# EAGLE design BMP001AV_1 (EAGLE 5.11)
AUTHOR: Nigel Batten; DATE: 15th Jun 2012; PRODUCT: AV XMega PDI - BMP001AV; RANGE: BreadMate; VERSION: Sch v1
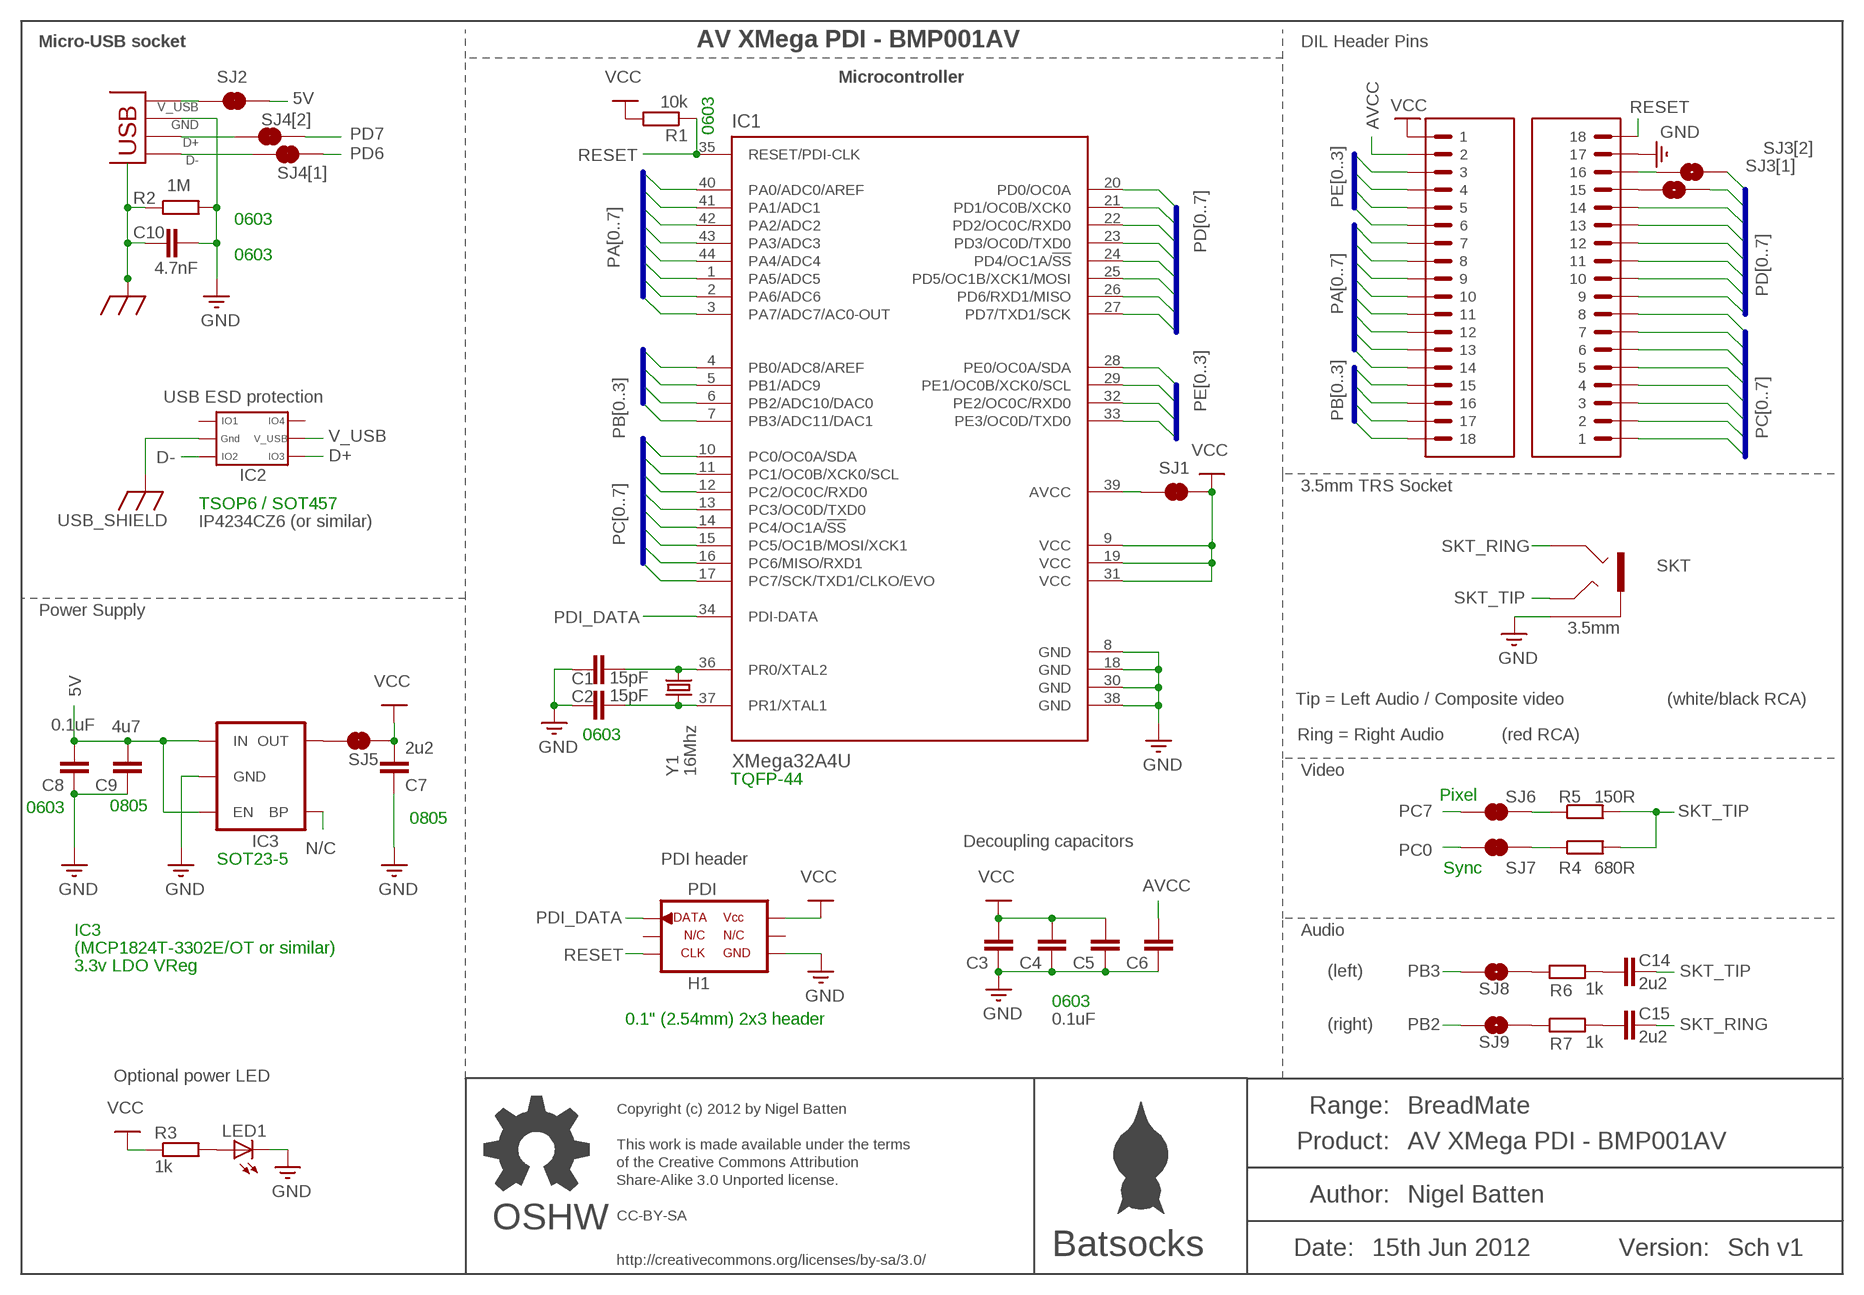
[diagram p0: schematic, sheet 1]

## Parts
C1  15pF  C_EU0603_TIGHT_MARK  [C0603TM]
C2  15pF  C_EU0603_TIGHT_MARK  [C0603TM]
C3  0.1uF  C_EU0603_TIGHT_MARK  [C0603TM]
C4  0.1uF  C_EU0603_TIGHT_MARK  [C0603TM]
C5  0.1uF  C_EU0603_TIGHT_MARK  [C0603TM]
C6  0.1uF  C_EU0603_TIGHT_MARK  [C0603TM]
C7  2u2  C_EU0805TM  [C0805TM]
C8  0.1uF  C_EU0603_TIGHT_MARK  [C0603TM]
C9  4u7  C_EU0805TM  [C0805TM]
C10  4.7nF  C_EU0603_TIGHT_MARK  [C0603TM]
C14  2u2  C_EU0603_TIGHT_MARK  [C0603TM]
C15  2u2  C_EU0603_TIGHT_MARK  [C0603TM]
H1  PDI  AVR_PDI_6  [AVR_ISP_6]
IC1  XMega32A4U  AT-XMEGA-XXA4-AUMEDIUM  [TQFP44_M]
IC2  USB_ESD  [SOT457]
IC3  LDO  V_REG_LDOSMD  [SOT23-5]
LED1  LED0603TU  [D0603TU]
R1  10k  RESISTOR0603_TIGHT_MARKED  [R0603TM]
R2  1M  RESISTOR0603_TIGHT_MARKED  [R0603TM]
R3  1k  RESISTOR0603TU  [R0603TU]
R4  680R  RESISTOR0603_TIGHT_MARKED  [R0603TM]
R5  150R  RESISTOR0603_TIGHT_MARKED  [R0603TM]
R6  1k  RESISTOR0603_TIGHT_MARKED  [R0603TM]
R7  1k  RESISTOR0603_TIGHT_MARKED  [R0603TM]
SJ1  SOLDERJUMPER_NCUNMARKED  [SJ_NC_U]
SJ2  SOLDERJUMPER_NCUNMARKED  [SJ_NC_U]
SJ3[1]  SOLDERJUMPER_NOSMALL_UNMARKED  [SJ_NO_SMALL_U]
SJ3[2]  SOLDERJUMPER_NOSMALL_UNMARKED  [SJ_NO_SMALL_U]
SJ4[1]  SOLDERJUMPER_NCSMALL_UNMARKED  [SJ_NC_SMALL_U]
SJ4[2]  SOLDERJUMPER_NCSMALL_UNMARKED  [SJ_NC_SMALL_U]
SJ5  SOLDERJUMPER_NCUNMARKED  [SJ_NC_U]
SJ6  SOLDERJUMPER_NCSMALL_UNMARKED  [SJ_NC_SMALL_U]
SJ7  SOLDERJUMPER_NCSMALL_UNMARKED  [SJ_NC_SMALL_U]
SJ8  SOLDERJUMPER_NOSMALL_UNMARKED  [SJ_NO_SMALL_U]
SJ9  SOLDERJUMPER_NOSMALL_UNMARKED  [SJ_NO_SMALL_U]
SKT  3.5mm  STEREO_SOCKET_UNSWITCHEDSMT  [SKT_STEREO_3.5MM_SMT_PJ313D]
U$2  HEADER_18BIGPADS_UNMARKED  [HEADER_18_BIGPADS_UNMARKED]
U$3  HEADER_18BIGPADS_UNMARKED  [HEADER_18_BIGPADS_UNMARKED]
U$4  LOGO_BATSOCKSTINY  [LOGO_BATSOCKS_TINY]
U$5  LOGO_OSHWTINY  [LOGO_OSHW_TINY]
USB  USB_SHIELD_8  [USB_MICRO_B]
Y1  16Mhz  CRYSTAL_4PINFA238_U  [CRYSTAL_FA238_U]

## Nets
5V: C8.2 C9.2 IC3.1(IN) IC3.3(EN) SJ2.2
AVCC: C6.2 IC1.39(AVCC) SJ1.2 U$2.P$2
D+: IC2.P$4(IO3) SJ4[2].1 USB.D+
D-: IC2.P$3(IO2) SJ4[1].1 USB.D-
GND: C1.2 C2.2 C3.1 C4.1 C5.1 C6.1 C7.2 C8.1 C9.1 C10.1 H1.P$6(GND) IC1.8(GND) IC1.18(GND) IC1.30(GND) IC1.38(GND) IC3.2(GND) LED1.K(C) R2.2 SKT.P$2(S) U$3.P$17 USB.GND
N$1: C2.1 IC1.37(PR1/XTAL1) Y1.P$1
N$2: C1.1 IC1.36(PR0/XTAL2) Y1.P$3
N$3: SJ3[1].1 U$3.P$15
N$4: SJ3[2].1 U$3.P$16
N$5: LED1.A R3.2
N$6: IC3.5(OUT) SJ5.1
N$7: R6.1 SJ8.2
N$8: R4.1 SJ7.2
N$9: R5.1 SJ6.2
N$11: R7.1 SJ9.2
N$12: C14.2 R6.2
N$13: C15.2 R7.2
N/C: IC3.4(BP)
PA0: IC1.40(PA0/ADC0/AREF) U$2.P$7
PA1: IC1.41(PA1/ADC1) U$2.P$8
PA2: IC1.42(PA2/ADC2) U$2.P$9
PA3: IC1.43(PA3/ADC3) U$2.P$10
PA4: IC1.44(PA4/ADC4) U$2.P$11
PA5: IC1.1(PA5/ADC5) U$2.P$12
PA6: IC1.2(PA6/ADC6) U$2.P$13
PA7: IC1.3(PA7/ADC7/AC0-OUT) U$2.P$14
PB0: IC1.4(PB0/ADC8/AREF) U$2.P$15
PB1: IC1.5(PB1/ADC9) U$2.P$16
PB2: IC1.6(PB2/ADC10/DAC0) SJ9.1 U$2.P$17
PB3: IC1.7(PB3/ADC11/DAC1) SJ8.1 U$2.P$18
PC0: IC1.10(PC0/OC0A/SDA) SJ7.1 U$3.P$1
PC1: IC1.11(PC1/OC0B/XCK0/SCL) U$3.P$2
PC2: IC1.12(PC2/OC0C/RXD0) U$3.P$3
PC3: IC1.13(PC3/OC0D/TXD0) U$3.P$4
PC4: IC1.14(PC4/OC1A/!SS) U$3.P$5
PC5: IC1.15(PC5/OC1B/MOSI/XCK1) U$3.P$6
PC6: IC1.16(PC6/MISO/RXD1) U$3.P$7
PC7: IC1.17(PC7/SCK/TXD1/CLKO/EVO) SJ6.1 U$3.P$8
PD0: IC1.20(PD0/OC0A) U$3.P$9
PD1: IC1.21(PD1/OC0B/XCK0) U$3.P$10
PD2: IC1.22(PD2/OC0C/RXD0) U$3.P$11
PD3: IC1.23(PD3/OC0D/TXD0) U$3.P$12
PD4: IC1.24(PD4/OC1A/!SS) U$3.P$13
PD5: IC1.25(PD5/OC1B/XCK1/MOSI) U$3.P$14
PD6: IC1.26(PD6/RXD1/MISO) SJ3[1].2 SJ4[1].2
PD7: IC1.27(PD7/TXD1/SCK) SJ3[2].2 SJ4[2].2
PDI_DATA: H1.P$1(DATA) IC1.34(PDI-DATA)
PE0: IC1.28(PE0/OC0A/SDA) U$2.P$3
PE1: IC1.29(PE1/OC0B/XCK0/SCL) U$2.P$4
PE2: IC1.32(PE2/OC0C/RXD0) U$2.P$5
PE3: IC1.33(PE3/OC0D/TXD0) U$2.P$6
RESET: H1.P$5(CLK) IC1.35(RESET/PDI-CLK) R1.1 U$3.P$18
SKT_RING: C15.1 SKT.P$3(R)
SKT_TIP: C14.1 R4.2 R5.2 SKT.P$4(T)
USB_SHIELD: C10.2 IC2.P$2(GND) R2.1 USB.SHIELD$1 USB.SHIELD$2(SHIELD$1) USB.SHIELD$3(SHIELD$1) USB.SHIELD$4(SHIELD$1) USB.SHIELD$5(SHIELD$1) USB.SHIELD$6(SHIELD$1) USB.SHIELD$7(SHIELD$1) USB.SHIELD$8(SHIELD$1) ; supply symbol labelled SHIELD
V_USB: IC2.P$5(V_USB) SJ2.1 USB.VBUS(V_USB)
VCC: C3.2 C4.2 C5.2 C7.1 H1.P$2(VCC_IO) IC1.9(VCC) IC1.19(VCC) IC1.31(VCC) R1.2 R3.1 SJ1.1 SJ5.2 U$2.P$1
Unconnected: H1.P$3(NC1) H1.P$4(NC2) IC2.P$1(IO1) IC2.P$6(IO4)

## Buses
PA[0..7]
PC[0..7]
PB[0..3]
PE[0..3]
PD[0..7]

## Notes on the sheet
- Micro-USB socket | DIL Header Pins
- Microcontroller
- 0603
- 0603
- 0603
- USB ESD protection
- 3.5mm TRS Socket
- TSOP6 / SOT457
- IP4234CZ6 (or similar)
- Power Supply
- Tip = Left Audio / Composite video | (white/black RCA)
- 0603 | Ring = Right Audio | (red RCA)
- Y1 | Video
- TQFP-44
- Pixel
- 0603 | 0805 | 0805
- Decoupling capacitors
- SOT23-5 | PDI header
- Sync
- IC3 | Audio
- (MCP1824T-3302E/OT or similar)
- 3.3v LDO VReg
- (left)
- 0603
- 0.1" (2.54mm) 2x3 header
- (right)
- Optional power LED
- Copyright (c) 2012 by Nigel Batten
- This work is made available under the terms
- of the Creative Commons Attribution
- Share-Alike 3.0 Unported license.
- CC-BY-SA
- OSHW
- http://creativecommons.org/licenses/by-sa/3.0/

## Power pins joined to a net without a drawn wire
GND$1: Y1.P$2(GND$1)
GND$2: Y1.P$4(GND$2)

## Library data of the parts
C1-C10 C14 C15 = Batten:C_EU
H1 = Batten:AVR_PDI_6
IC1 = Batten:AT-XMEGA-XXA4-AU: ATxMega a4 Series
IC2 = Batten:USB_ESD
IC3 = Batten:V_REG_LDO: Voltage Regulator LDO Standard 150mA LDO voltage regulator in SOT-23 layout. Micrel part MIC5205. BP (by-pass) pin is used to lower output noise with 470pF cap.
LED1 = Batten:LED: LED
R1-R7 = Batten:RESISTOR
SJ1 SJ2 SJ4[1] SJ4[2] SJ5-SJ7 = Batten:SOLDERJUMPER_NC: Solder Jumper
SJ3[1] SJ3[2] SJ8 SJ9 = Batten:SOLDERJUMPER_NO: Solder Jumper
SKT = Batten:STEREO_SOCKET_UNSWITCHED
U$2 U$3 = Batten:HEADER_18
U$4 = Batten:LOGO_BATSOCKS
U$5 = Batten:LOGO_OSHW
USB = Batten:USB_SHIELD_8
Y1 = Batten:CRYSTAL_4PIN

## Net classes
1 power: width 0.406 mm, drill 0.35 mm, clearance 0.203 mm

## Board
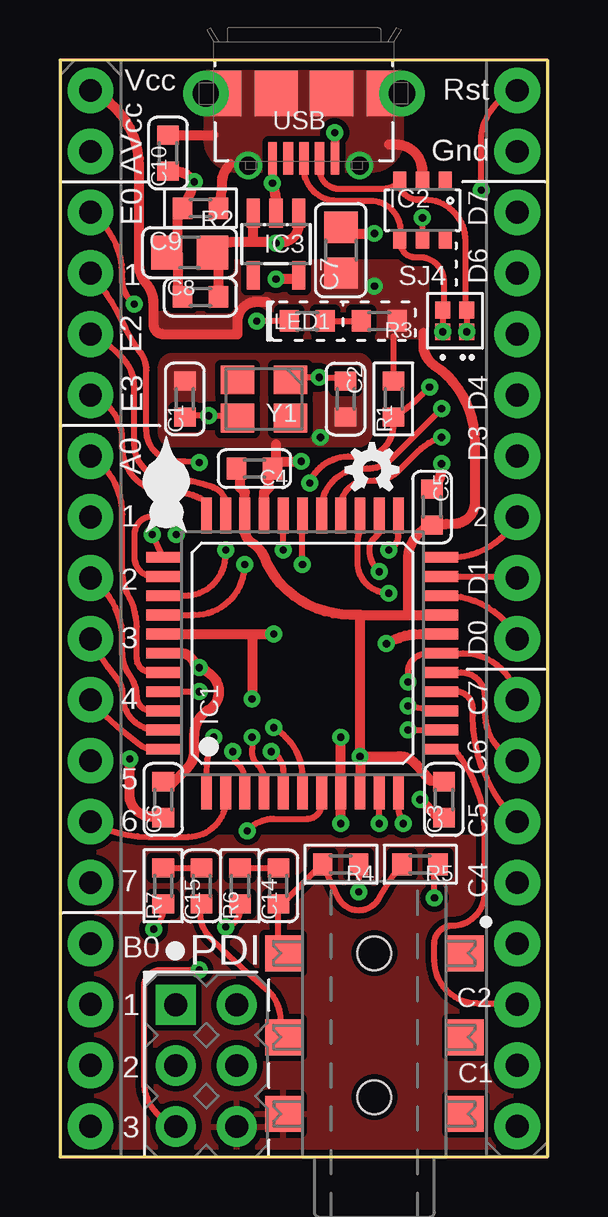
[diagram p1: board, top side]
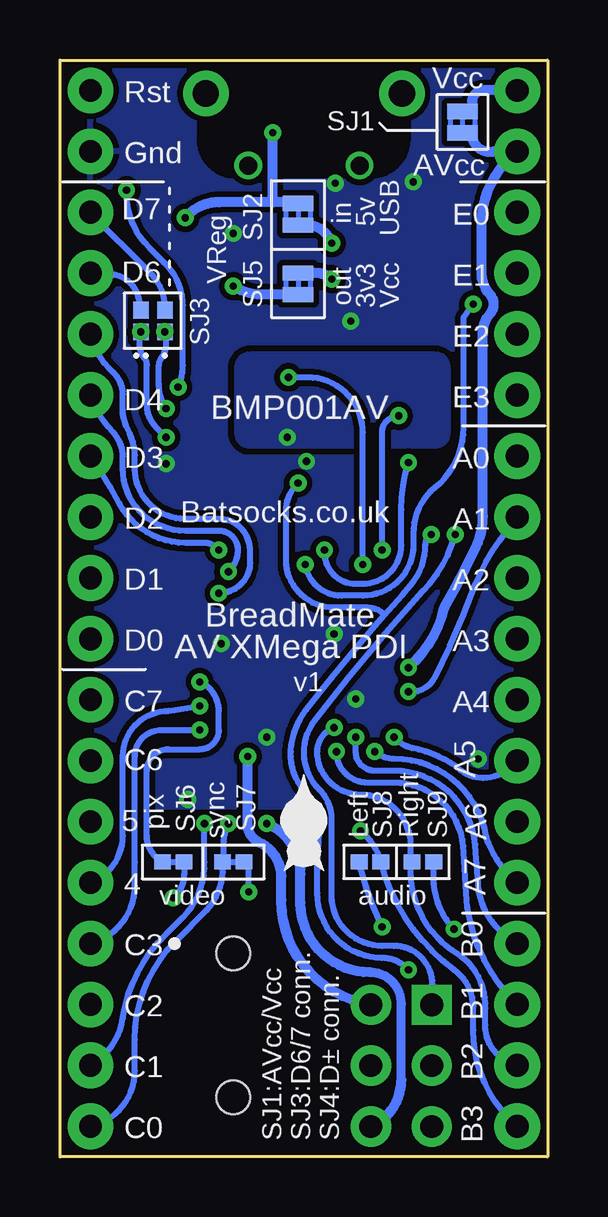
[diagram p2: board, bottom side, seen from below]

Size 20.32 x 45.72 mm. Coordinates in mm from the lower left corner, seen from the top.
Outline: 0,0 20.32,0 20.32,45.72 0,45.72 0,0
Copper layers (1*16): Top 0.035mm / dielectric 1.5mm / Bottom 0.035mm
Design rules "ITead_rule *": minimum track width 8mil, minimum drill 0.3mm, track to track 0.235mm, track to pad 0.2388mm, pad to pad 0.2388mm, via to via 0.2388mm, smd to smd 0.2388mm, copper to edge 10mil, drill to drill 10mil, minimum pad ring 8mil, minimum via ring 8mil, stop-mask expansion 4mil, vias tented up to drill 0.35mm, thermal gap 10mil
tRestrict: area 11.1,13.3 to 12.3,14.5; 3 lines
bRestrict: 8 lines

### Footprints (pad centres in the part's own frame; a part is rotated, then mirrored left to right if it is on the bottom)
C0603TM = smd 0.8 x 0.9: 1 -0.75,0; 2 0.75,0
C0805TM = smd 1.3 x 1.4: 1 -0.95,0; 2 0.95,0
AVR_ISP_6 = drill 0.95 pad 1.676 square: P$1 -1.27,2.54 | drill 0.95 pad 1.676 round: P$2 1.27,2.54; P$3 -1.27,0; P$4 1.27,0; P$5 -1.27,-2.54; P$6 1.27,-2.54
TQFP44_M = smd 1.5 x 0.45: 1 -5.75,4; 2 -5.75,3.2; 3 -5.75,2.4; 4 -5.75,1.6; 5 -5.75,0.8; 6 -5.75,0; 7 -5.75,-0.8; 8 -5.75,-1.6; 9 -5.75,-2.4; 10 -5.75,-3.2; 11 -5.75,-4; 23 5.75,-4; 24 5.75,-3.2; 25 5.75,-2.4; 26 5.75,-1.6; 27 5.75,-0.8; 28 5.75,0; 29 5.75,0.8; 30 5.75,1.6; 31 5.75,2.4; 32 5.75,3.2; 33 5.75,4 | smd 0.45 x 1.5: 12 -4,-5.75; 13 -3.2,-5.75; 14 -2.4,-5.75; 15 -1.6,-5.75; 16 -0.8,-5.75; 17 0,-5.75; 18 0.8,-5.75; 19 1.6,-5.75; 20 2.4,-5.75; 21 3.2,-5.75; 22 4,-5.75; 34 4,5.75; 35 3.2,5.75; 36 2.4,5.75; 37 1.6,5.75; 38 0.8,5.75; 39 0,5.75; 40 -0.8,5.75; 41 -1.6,5.75; 42 -2.4,5.75; 43 -3.2,5.75; 44 -4,5.75
SOT457 = smd 0.8 x 0.55: P$1 -1.2,0.95; P$2 -1.2,0; P$3 -1.2,-0.95; P$4 1.2,-0.95; P$5 1.2,0; P$6 1.2,0.95
SOT23-5 = smd 0.55 x 1.2: 1 -0.95,-1.3; 2 0,-1.3; 3 0.95,-1.3; 4 0.95,1.3; 5 -0.95,1.3
D0603TU = smd 0.8 x 0.9: A 0.75,0; K -0.75,0
R0603TM = smd 0.8 x 0.9: 1 -0.75,0; 2 0.75,0
R0603TU = smd 0.8 x 0.9: 1 -0.75,0; 2 0.75,0
SJ_NC_U = smd 0.635 x 1.27: 1 -0.45,0; 2 0.45,0
SJ_NO_SMALL_U = smd 0.7 x 0.635: 1 -0.45,0; 2 0.45,0
SJ_NC_SMALL_U = smd 0.7 x 0.635: 1 -0.45,0; 2 0.45,0
SKT_STEREO_3.5MM_SMT_PJ313D = smd 1.5 x 1.5: P$2 1.8,3.8; P$3 5,3.8; P$4 8.5,3.8; P$22 1.8,-3.8; P$33 5,-3.8; P$44 8.5,-3.8 | hole 1.4: 2.5,0; 8.5,0
HEADER_18_BIGPADS_UNMARKED = drill 0.95 pad 1.905 round: P$1 -21.59,0; P$2 -19.05,0; P$3 -16.51,0; P$4 -13.97,0; P$5 -11.43,0; P$6 -8.89,0; P$7 -6.35,0; P$8 -3.81,0; P$9 -1.27,0; P$10 1.27,0; P$11 3.81,0; P$12 6.35,0; P$13 8.89,0; P$14 11.43,0; P$15 13.97,0; P$16 16.51,0; P$17 19.05,0; P$18 21.59,0
USB_MICRO_B = smd 0.4 x 1.35: D+ 0,-2.7; D- 0.65,-2.7; ID -0.65,-2.7 | smd 0.35 x 1.35: GND -1.3,-2.7; VBUS 1.3,-2.7 | drill 1.1 pad 1.9 round: SHIELD$1 -4.085,0; SHIELD$2 4.085,0 | drill 0.75 pad 1.15 round: SHIELD$3 -2.32,-3; SHIELD$4 2.32,-3 | smd 1.47 x 1.9: SHIELD$5 -3.35,0; SHIELD$8 3.35,0 | smd 1.8 x 1.9: SHIELD$6 -1.15,0; SHIELD$7 1.15,0
CRYSTAL_FA238_U = smd 1.4 x 1.2: P$1 -1.1,-0.8; P$2 1.1,-0.8; P$3 1.1,0.8; P$4 -1.1,0.8

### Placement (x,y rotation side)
C1  5.2,31.59 90 top
C2  11.9,31.59 270 top
C3  16,14.89 90 top
C4  8.1,28.69 180 top
C5  15.5,27.09 270 top
C6  4.3,14.89 90 top
C7  11.7,37.79 90 top
C8  5.85,35.84 0 top
C9  5.4,37.69 0 top
C10  4.5,41.84 90 top
C14  9.1,11.29 90 top
C15  5.9,11.29 90 top
H1  6.1,3.8 0 top
IC1  10.1,20.99 90 top
IC2  15.11,39.46 270 top
IC3  9,38.04 180 top
LED1  10.3,34.84 0 top
R1  13.9,31.59 90 top
R2  5.85,39.54 180 top
R3  13.3,34.84 180 top
R4  11.7,12.19 180 top
R5  15,12.19 180 top
R6  7.5,11.29 90 top
R7  4.3,11.29 90 top
SJ1  3.56,43.13 270 bottom
SJ2  10.4,39.29 270 bottom
SJ3[1]  16.95,34.84 270 bottom
SJ3[2]  15.95,34.84 270 bottom
SJ4[1]  16.95,34.84 270 top
SJ4[2]  15.95,34.84 270 top
SJ5  10.4,36.39 270 bottom
SJ6  15.6,12.29 0 bottom
SJ7  13.1,12.29 0 bottom
SJ8  7.4,12.29 180 bottom
SJ9  5.2,12.29 0 bottom
SKT  13.1,-0.01 90 top
U$2  1.27,22.86 270 top
U$3  19.05,22.86 90 top
U$4  4.43,28.08 0 top
U$5  13,28.64 0 top
U$6  [LOGO_BATSOCKS_TINY]  10.16,13.96 0 bottom
USB  10.16,44.32 0 top
Y1  8.5,31.59 180 top

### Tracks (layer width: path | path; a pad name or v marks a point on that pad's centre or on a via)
5V  (via drill 0.3)
  Top 0.406: 8.05,38.14 7.25,38.14 arc53 C9.2 6.6,37.39 C8.2 | 8.05,38.14 IC3.3 | 8.05,38.14 9,38.14 | 9,38.14 9.1,38.14 arc106 9.95,38.94 arc-33 IC3.1 | 9,38.14 v9,38.09
  Bottom 0.406: SJ2.2 10.05,38.84 arc71 v9,38.09
AVCC  (via drill 0.3)
  Top 0.406: 4.65,15.54 5.3,16.19 arc41 5.6,16.89 5.6,17.59 arc-59 6.2,18.64 arc107 6.35,20.04 arc21 v5.8,20.39 arc-46 5.6,20.59 arc76 4.9,20.99 arc-17 IC1.39 | 4.65,15.54 4.5,15.54 | C6.2 4.65,15.54
  Bottom 0.406: SJ1.2 3.25,42.67 3.15,42.54 arc-90 2.3,41.89 1.29,41.89 U$2.P$2 arc-52 2.75,38.89 2.75,36.79 arc-37 2.4,35.94 arc41 2.25,35.54 arc41 2.4,35.14 arc-43 2.7,34.29 2.7,26.69 arc26 3,25.39 arc3 4.3,22.89 arc35 v5.8,20.39
D+
  Top 0.254: USB.D+ 10.16,41.13 arc86 11.55,39.84 12.95,39.84 arc-90 14.2,38.59 14.2,38.09 | SJ4[2].1 16,35.39 16,36.49 arc90 15,37.49 14.8,37.49 arc-90 14.2,38.09 | IC2.P$4 14.17,38.26 14.2,38.09
D-
  Top 0.254: USB.D- 10.81,41.18 arc90 11.65,40.34 13.4,40.34 arc46 IC2.P$3 14.15,40.64 arc90 14.9,39.89 15.2,39.89 arc-90 16.9,38.19 16.9,35.34 SJ4[1].1
GND  (via drill 0.3)
  Top 0.254: LED1.K v8.2,34.84
  Top 0.356: 8.86,40.73 USB.GND
  Top 0.406: v11.7,17.49 IC1.8 v11.7,13.89 | IC1.38 8,21.79 | 8,21.79 v8.9,21.79 | IC1.30 8.5,27.69 8.7,27.89 8.7,28.44 8.88,28.61 | 8.88,28.61 8.95,28.69 9,28.69 9,28.99 | 8,21.79 v8,19.09 | IC1.18 15,21.79 arc32 v13.6,21.39 | 9,28.99 9,29.69 | v13.1,38.49 12,38.49 12,38.54 C7.2 | C6.1 arc-11 4.2,14.09 arc49 3.9,14.19 arc-96 2.9,15.09 v2.9,16.59 | v15.9,28.89 15.9,28.69 arc-50 C5.1 | C10.1 4.7,41.09 arc-53 v5.6,40.64 arc-20 R2.2 4.9,39.49 4.9,37.69 | C8.1 4.9,35.89 4.9,37.69 | C9.1 4.9,37.69 | IC3.2 9,39.79 arc21 v8.85,40.59 arc-51 8.86,40.73 | 8.88,28.61 C4.1 | 9,28.99 v10.05,28.99 | C3.1 16,14.29 15.7,14.19 v15,14.89
  Bottom 0.375: 6.1,3.19 6.1,6.39 arc-90 7.4,7.69
  Bottom 0.406: v11.7,13.89 arc67 10.3,11.79 10.3,10.59 arc-90 7.4,7.69 | H1.P$6 arc-67 6.1,3.19
  other vias: 10.85,29.99
  pour Bottom (rank 3): 0,45.72 5.59,45.72 5.59,42.42 arc90 7.37,40.64 13.21,40.64 arc90 14.73,42.67 14.73,45.72 20.32,45.72 20.32,14.6 0,14.6
  pour Top (rank 2, no thermals): 4.2,30.19 4.2,32.89 arc-90 4.7,33.39 12.4,33.39 arc-90 12.9,32.89 12.9,30.19 arc-90 12.4,29.69 4.7,29.69 arc-90
  pour Top: 0,-0.01 20.3,-0.01 20.3,13.29 0,13.29
N$1  (via drill 0.3)
  Top 0.254: IC1.37 5.6,22.59 arc90 v7.7,24.69 | C2.1 arc53 11.6,32.49 v10.8,32.49 10,32.49 arc28 Y1.P$1
  Bottom 0.254: v7.7,24.69 7.7,30.19 arc-90 10,32.49 v10.8,32.49
N$2  (via drill 0.3)
  Top 0.254: IC1.36 5.2,23.39 arc90 6.9,25.09 v6.9,25.29 | C1.1 arc-28 5.4,30.89 v6.2,30.89 7,30.89 arc-28 Y1.P$3
  Bottom 0.254: v6.9,25.29 6.9,30.19 arc90 v6.2,30.89
N$3
  Bottom 0.254: SJ3[1].1 16.95,35.34 17,35.39 17,35.49 arc-90 18.3,36.79 19.01,36.79 U$3.P$15
N$4
  Bottom 0.254: U$3.P$16 19.05,39.34 16.6,36.89 arc47 15.95,35.39 SJ3[2].1
N$5
  Top 0.254: LED1.A R3.2
N$6  (via drill 0.3)
  Top 0.406: 9.9,36.79 IC3.5 9.95,36.59 v9,36.59 | 9.9,36.79
  Bottom 0.406: SJ5.1 9.65,36.84 arc42 v9,36.59
N$7  (via drill 0.3)
  Top 0.254: R6.1 7.5,10.29 arc-81 v6.9,9.59
  Bottom 0.254: SJ8.2 7.8,12.09 arc-12 v6.9,9.59
N$8  (via drill 0.3)
  Top 0.254: R4.1 v12.45,11.04
  Bottom 0.254: v12.45,11.04 12.45,12.29 SJ7.2
N$9  (via drill 0.3)
  Top 0.254: v15.6,10.79 15.6,12.19 R5.1
  Bottom 0.254: SJ6.2 15.15,11.79 arc48 v15.6,10.79
N$11  (via drill 0.3)
  Top 0.254: R7.1 4.3,10.34 arc-50 v3.9,9.49
  Bottom 0.254: SJ9.2 4.75,11.64 arc-43 v3.9,9.49
N$12
  Top 0.254: R6.2 C14.2
N$13
  Top 0.254: R7.2 C15.2
PA0
  Top 0.254: IC1.40 3.8,20.19 arc-90 3.2,20.79 3.2,22.09 arc28 2.9,23.29 arc-28 2.6,24.49 2.6,26.79 arc58 U$2.P$7
PA1  (via drill 0.3)
  Top 0.254: IC1.41 v5.8,19.39
  Bottom 0.254: U$2.P$8 2,25.69 arc-15 3,23.89 arc8 4.7,19.99 arc58 5.6,19.39 arc9 v5.8,19.39
PA2
  Top 0.254: IC1.42 3.8,18.59 arc-90 3.2,19.19 arc37 2.9,20.09 arc-37 2.6,20.99 2.6,21.59 arc55 U$2.P$9
PA3
  Top 0.254: IC1.43 4,17.79 arc-90 2.6,19.29 arc41 2.4,19.89 arc-10 U$2.P$10
PA4
  Top 0.254: IC1.44 3.9,16.99 arc-37 3.3,17.19 arc-11 U$2.P$11
PA5  (via drill 0.3)
  Top 0.254: IC1.1 6.1,16.09 arc-24 v6.4,17.49
  Bottom 0.254: U$2.P$12 arc53 2.7,15.79 arc35 3.6,16.09 arc-17 4.55,16.69 arc-12 5.65,17.04 arc33 6.3,17.39 v6.4,17.49
PA6
  Top 0.254: IC1.2 arc-101 5.35,13.34 3.65,13.34 arc-30 U$2.P$13
PA7  (via drill 0.3)
  Top 0.254: IC1.3 7.7,15.69 arc46 7.4,16.39 arc-49 v7.2,16.89
  Bottom 0.254: U$2.P$14 1.8,11.99 arc26 2.55,13.34 arc-80 6.4,16.59 arc41 v7.2,16.89
PB0  (via drill 0.3)
  Top 0.254: IC1.4 8.5,15.69 arc46 8.2,16.39 arc-56 8,16.99 v8,17.49
  Bottom 0.254: v8,17.49 8,16.89 arc-90 7.2,16.09 6.4,16.09 arc90 3,12.69 2.9,11.39 arc-57 U$2.P$15
PB1  (via drill 0.3)
  Top 0.254: IC1.5 9.3,16.09 arc64 v8.8,16.89
  Bottom 0.254: v8.8,16.89 arc-90 7.5,15.59 6.4,15.59 arc90 3.5,12.69 3.4,10.99 arc-43 U$2.P$16
PB2  (via drill 0.3)
  Top 0.254: IC1.6 10.1,15.79 arc59 v8.9,17.89
  Bottom 0.254: U$2.P$17 arc77 2.6,5.49 2.6,6.19 arc-61 3.8,8.49 arc15 4.6,9.14 arc41 5.7,11.69 5.7,12.29 | v8.9,17.89 arc-70 9.6,16.89 arc-90 7.8,15.09 arc90 5.7,12.99 5.7,12.29 | 5.7,12.29 SJ9.1
PB3  (via drill 0.3)
  Top 0.254: IC1.7 10.9,14.69 arc-90 10.3,14.09 8.9,14.09 arc49 v7.8,13.59
  Bottom 0.254: U$2.P$18 arc49 3.1,5.29 3.1,6.29 arc-53 3.9,7.79 arc16 5.6,9.49 arc22 SJ8.1 arc-37 v7.8,13.59
PC0  (via drill 0.3)
  Top 0.254: v13.3,13.89 IC1.10
  Bottom 0.254: U$3.P$1 arc-77 17.2,3.59 17.2,4.89 arc45 15.5,8.99 14.2,10.29 arc-49 SJ7.1 13.5,12.29 13.5,12.99 arc25 v13.3,13.89
PC1  (via drill 0.3)
  Top 0.254: IC1.11 14.1,14.69 arc28 v14.3,13.89
  Bottom 0.254: U$3.P$2 arc-51 17.7,5.79 arc37 15.9,9.29 15.2,9.99 arc-47 14.3,12.29 v14.3,13.89
PC2
  Top 0.254: U$3.P$3 19.01,6.39 17.4,6.39 arc-90 15.6,8.19 15.6,8.89 arc-90 16.35,9.64 arc90 17.7,10.99 arc2 17.7,11.59 arc1 17.7,13.58 arc33 16.8,16.49 arc6 16.5,16.89 arc83 IC1.12
PC3  (via drill 0.3)
  Top 0.254: v14.5,17.79 IC1.13
  Bottom 0.254: v14.5,17.79 16.1,17.79 arc-90 17.2,16.69 17.2,12.29 17.2,11.29 arc75 U$3.P$4
PC4  (via drill 0.3)
  Top 0.254: v14.5,18.79 IC1.14
  Bottom 0.254: v14.5,18.79 15.8,18.59 arc-90 17.7,16.69 17.7,13.39 arc69 U$3.P$5
PC5
  Top 0.254: IC1.15 16.5,19.39 arc-90 17.2,18.69 17.2,18.39 arc45 U$3.P$6
PC6
  Top 0.254: IC1.16 16.7,20.19 arc-90 17.7,19.19 17.7,18.49 arc69 U$3.P$7
PC7  (via drill 0.3)
  Top 0.254: U$3.P$8 arc82 16.8,20.99 IC1.17 15.3,20.99 arc90 14.5,20.19 v14.5,19.79
  Bottom 0.254: SJ6.1 arc61 16.7,13.39 16.7,16.09 arc90 15.8,16.99 14.5,16.99 arc-90 13.7,17.79 13.7,18.59 arc-67 v14.5,19.79
PD0
  Top 0.254: IC1.20 16.1,23.39 arc-63 U$3.P$9
PD1
  Top 0.254: IC1.21 18.99,24.19 U$3.P$10
PD2
  Top 0.254: IC1.22 16.3,24.99 arc63 U$3.P$11
PD3  (via drill 0.3)
  Top 0.254: IC1.23 14.1,25.89 arc-67 v13.7,25.29
  Bottom 0.254: v13.7,25.29 arc-53 14.3,25.59 15.1,25.59 arc62 17.85,27.24 arc-7 U$3.P$12
PD4  (via drill 0.3)
  Top 0.254: IC1.24 arc-82 13.1,25.79 arc53 12.9,25.39 12.9,25.29 arc48 v13.3,24.39
  Bottom 0.254: U$3.P$13 arc-25 18.1,30.19 arc44 17.7,29.19 17.7,28.69 arc-90 15.1,26.09 13.7,26.09 arc90 12.9,25.29 arc48 v13.3,24.39
PD5  (via drill 0.3)
  Top 0.254: IC1.25 arc-38 12.5,26.09 arc19 12.4,25.49 12.4,24.79 arc90 v13.7,23.49
  Bottom 0.254: U$3.P$14 arc-34 18.1,32.69 arc48 17.7,31.79 17.7,31.14 arc-29 17.5,30.34 arc26 17.2,29.24 17.2,28.69 arc-90 15.1,26.59 13.7,26.59 arc90 12.4,25.29 12.4,24.79 arc90 v13.7,23.49
PD6  (via drill 0.3)
  Top 0.254: IC1.26 11.7,27.09 arc-90 12.8,28.19 13.1,28.19 arc44 14.1,28.59 14.9,29.39 arc-28 v15.9,29.99
  Bottom 0.254: SJ3[1].2 17,34.34 17,33.79 arc-30 16.8,33.29 arc37 16.7,32.99 16.7,31.39 arc-44 16.3,30.39 v15.9,29.99
  other vias: 16.95,34.39
PD7  (via drill 0.3)
  Top 0.254: IC1.27 10.9,26.99 arc-90 12.6,28.69 12.8,28.69 arc49 13.9,29.19 v15.9,31.19
  Bottom 0.254: SJ3[2].2 15.9,34.34 15.9,33.79 arc30 16.1,33.29 arc-37 16.2,32.99 16.2,32.19 arc-33 v15.9,31.19
  other vias: 15.95,34.39
PDI_DATA  (via drill 0.3)
  Top 0.254: IC1.34 4.3,24.99 v3.85,25.94
  Bottom 0.254: v3.85,25.94 arc30 5.2,23.59 arc-5 9.7,18.19 arc-83 9.5,15.29 arc45 9,14.09 9,10.89 arc-90 6.9,8.79 6.4,8.79 arc90 4.8,7.19 4.8,6.37 H1.P$1
PE0  (via drill 0.3)
  Top 0.254: v10.1,24.69 IC1.28 | v3.1,35.54 2.95,35.69 arc-48 2.6,36.59 arc56 U$2.P$3
  Bottom 0.254: v3.1,35.54 3.5,34.99 3.5,30.39 arc50 4.7,27.89 arc-51 5.6,25.99 5.6,25.49 arc90 7.7,23.39 8.6,23.39 arc68 10,24.34 v10.1,24.69
PE1  (via drill 0.3)
  Top 0.254: v9.3,25.29 IC1.29 | U$2.P$4 1.7,36.29 arc-14 2.5,34.99 arc10 3.3,33.59 arc-41 3.6,32.79 3.6,30.29 arc90 4.9,28.99 arc-6 v5.8,28.94
  Bottom 0.254: 9.3,25.19 v9.3,25.29 arc-94 8,23.89 7.7,23.89 arc-90 6.1,25.49 6.1,26.99 arc17 v5.8,28.94
PE2
  Top 0.254: 6.9,27.09 IC1.32 6.9,27.29 arc64 6.4,27.89 arc18 4.5,28.29 arc-90 3.1,29.69 3.1,32.09 arc50 2.5,33.39 1.9,33.99 arc39 U$2.P$5
PE3
  Top 0.254: 6.1,27.19 IC1.33 6.1,27.29 arc37 4.9,27.69 4.5,27.69 arc-90 2.6,29.59 2.6,29.89 arc71 U$2.P$6
RESET  (via drill 0.3)
  Top 0.254: IC1.35 3.9,24.19 arc-90 3.1,24.99 3.1,25.94 arc-94 3.9,26.69 arc-69 v4.85,25.94 | R1.1 13.9,30.49 arc-90 12.6,29.19 12,29.19 arc69 v10.4,28.09 | v15.4,32.09 15.1,31.79 arc-13 R1.1 | R1.1 13.95,30.89 arc180 R1.1 | v17.55,40.29 17.55,42.34 arc-71 U$3.P$18 | v5.8,7.79 4.2,7.79 arc90 3.5,7.09 3.5,3.19 arc69 H1.P$5
  Bottom 0.254: v10.4,28.09 arc-45 10.9,26.89 10.9,24.89 arc-90 8.9,22.89 7.5,22.89 arc46 6.8,22.59 | v15.4,32.09 arc-25 15.2,32.99 15.2,35.49 arc-48 16,37.29 16.6,37.89 arc47 v17.55,40.29 | v5.8,7.79 arc-49 6.9,8.29 arc90 9.6,10.99 9.6,11.99 9.5,13.89 arc-45 10,15.09 arc48 10.7,16.89 arc35 10.05,18.64 arc3 6.8,22.59 | 6.8,22.59 arc-3 5.7,23.84 arc-39 5.1,25.49 arc58 v4.85,25.94
SKT_RING
  Top 0.254: C15.1 arc60 6.3,9.09 arc4 8.6,6.99 arc-50 9.2,5.69 9.2,5.09 SKT.P$3
SKT_TIP
  Top 0.254: SKT.P$4 9.1,8.69 C14.1 9.4,10.69 10.8,12.09 arc-5 R4.2 11.6,10.79 arc124 13.3,10.79 arc-12 R5.2
USB_SHIELD
  Top 0.406: USB.SHIELD$3 7.8,41.28 | IC2.P$2 15.1,41.07 15.1,41.09 arc90 14,42.19 13.7,42.19 | 7.1,41.39 arc45 6.75,40.54 arc-17 R2.1 | C10.2 6.4,42.59
  pour Top (isolate 0.254, no thermals): 6.1,45.16 6.1,42.42 arc90 7.37,41.15 12.95,41.15 arc90 14.22,42.42 14.22,45.16
V_USB  (via drill 0.3)
  Top 0.254: IC2.P$5 15.1,38.64 v15.1,39.14
  Top 0.356: USB.VBUS v11.46,42.68 v11.45,42.69
  Bottom 0.406: 11.45,39.79 v11.45,42.69 | 11.45,39.79 13.7,39.79 arc-50 v15.1,39.14 | 11.45,39.79 10.4,39.79 SJ2.1
VCC  (via drill 0.3)
  Top 0.254: R1.2 13.9,34.19
  Top 0.406: 14.5,22.59 IC1.19 | 15.15,34.34 15.15,33.84 arc56 15.6,32.99 arc-56 17.3,29.79 17.3,27.29 arc-90 16.4,26.39 arc6 C5.2 arc69 14.5,24.89 14.5,22.59 | 12.5,22.59 12.1,22.59 arc-64 8.6,24.79 arc42 8,25.59 arc-54 7.7,26.09 arc-8 7.7,26.29 IC1.31 7.7,27.69 7.5,27.89 7.5,28.44 7.25,28.69 C4.2 | v12.5,16.69 IC1.9 | v12.5,16.69 12.5,22.59 | U$2.P$1 arc-65 3.3,41.29 3.3,37.19 arc41 3.6,36.39 arc-41 3.9,35.59 3.9,34.69 arc90 4.3,34.29 7.4,34.29 7.4,34.84 arc-90 8.2,35.64 8.6,35.64 | 12.5,22.59 14.5,22.59 | C3.2 15.4,15.69 14.8,16.39 arc52 14.1,16.69 v12.5,16.69
  Bottom 0.406: U$2.P$1 2.69,44.45 arc-90 3.15,43.99 3.15,43.62 SJ1.1 | H1.P$2 arc81 11.1,10.69 11.1,11.69 arc-65 12,13.09 arc60 12.5,13.79 v12.5,16.69 | SJ5.2 11.9,35.94 arc33 v13.1,36.29
  pour Top (rank 3, no thermals): 7.17,37.29 15.25,37.29 15.25,34.19 8.2,34.19 8.2,35.19 7.45,35.19 7.45,34.32 4.53,34.32 arc-90 3.92,34.79 3.92,35.14 7.2,35.14

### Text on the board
tPlace: Rst | Vcc | Gnd | AVcc | E0 | D7 | SJ4 | 1 | D6 | E2 | E3 | D4 | D3 | A0 | 1 | 2 | 2 | D1 | 3 | D0 | 4 | C7 | C6 | 5 | 6 | C5 | 7 | C4 | B0 | PDI | C2 | 1 | C1 | 2 | 3
bPlace: Vcc | Rst | SJ1 | AVcc | Gnd | E0 | 5v | in | D7 | USB | SJ2 | E1 | out | VReg | D6 | E2 | Vcc | 3v3 | SJ5 | SJ3 | E3 | BMP001AV | D4 | A0 | D3 | A1 | Batsocks.co.uk | D2 | A2 | D1 | A3 | BreadMate | AV XMega PDI | D0 | A4 | v1 | C7 | A5 | C6 | SJ7 | SJ6 | pix | 5 | A6 | SJ9 | Right | SJ8 | Left | sync | A7 | audio | video | 4 | B0 | C3 | B1 | C2 | B2 | C1 | B3 | SJ4:D± conn. | SJ3:D6/7 conn. | SJ1:AVcc/Vcc | C0
Document: Top ground fill is | only joined to main | ground at PDI hdr.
